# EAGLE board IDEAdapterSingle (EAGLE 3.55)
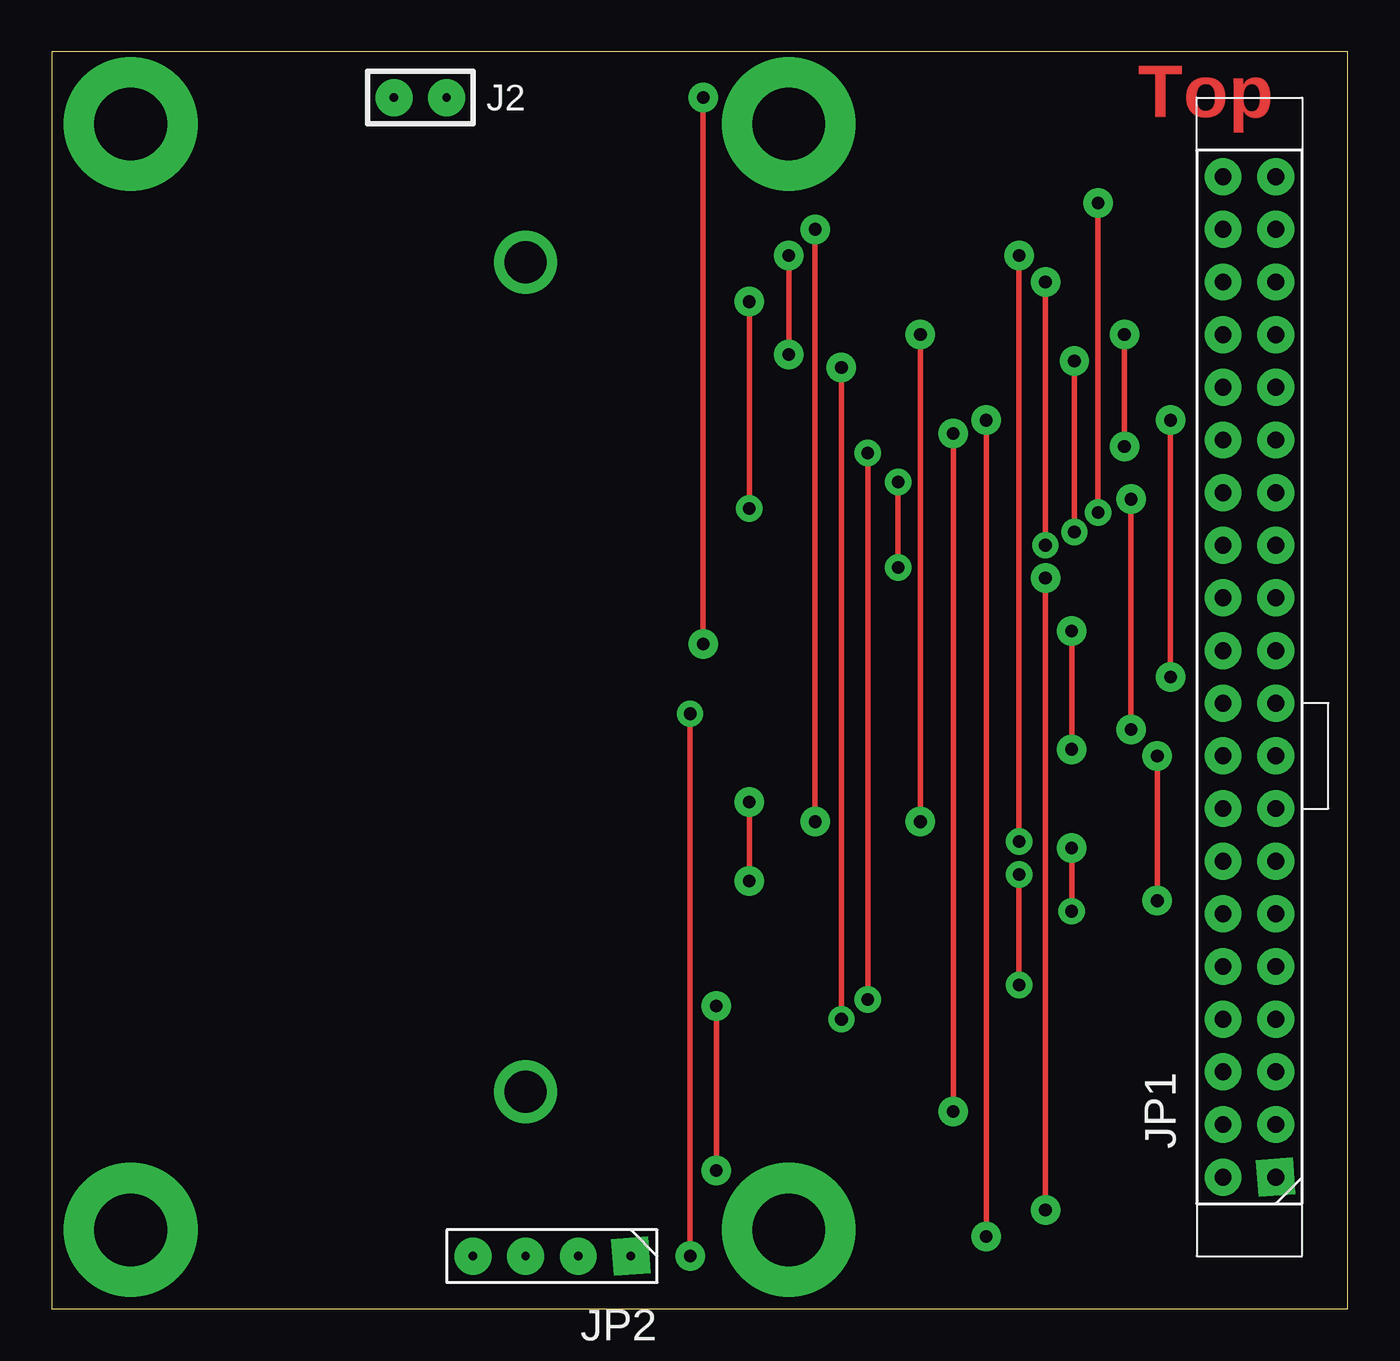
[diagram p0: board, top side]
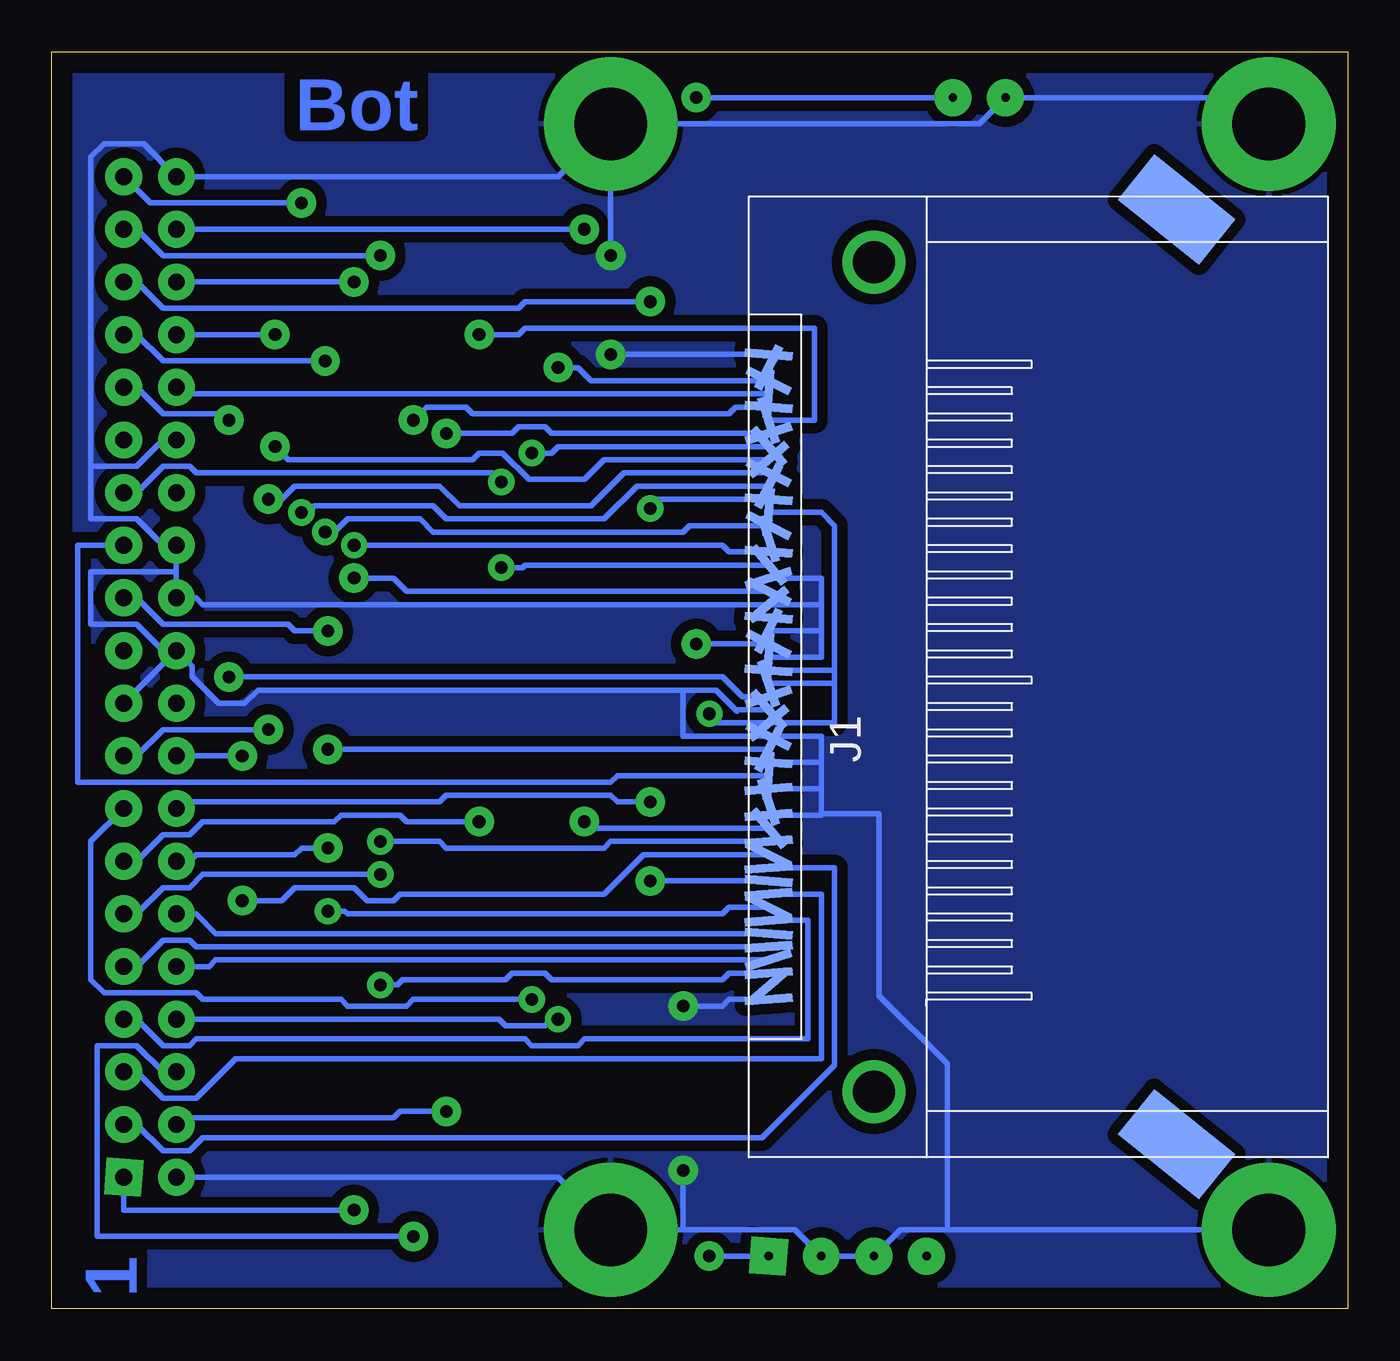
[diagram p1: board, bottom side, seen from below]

Size 62.53 x 60.63 mm. Coordinates in mm from the lower left corner, seen from the top.
Outline: 0,0 62.53,0 62.53,60.63 0,60.63 0,0
Copper layers used: Top, Bottom

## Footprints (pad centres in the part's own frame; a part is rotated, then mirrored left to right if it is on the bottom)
SMT = drill 2.032 pad 3.048 round: @1 -20.003,-5.08; @2 20.003,-5.08 | smd 2.794 x 5.004 rotated 321.2: @3 -22.543,-19.685; @4 22.543,-19.685 | smd 0.406 x 2.311 rotated 4.3:  -15.557,0;  -4.128,0 | smd 0.406 x 2.311 rotated 4.4:  -14.287,0;  8.572,0 | smd 0.406 x 2.311 rotated 4.5:  -13.018,0;  -9.842,0 | smd 0.406 x 2.311 rotated 4.6:  -11.748,0;  2.857,0 | smd 0.406 x 2.311 rotated 4.7:  -10.477,0;  -9.207,0;  15.557,0 | smd 0.406 x 2.311 rotated 4.8:  -7.938,0 | smd 0.406 x 2.311 rotated 4.9:  -6.668,0 | smd 0.406 x 2.311 rotated 5:  -5.397,0 | smd 0.406 x 2.311 rotated 26.8:  -2.857,0 | smd 0.406 x 2.311 rotated 49.3:  -1.587,0 | smd 0.406 x 2.311 rotated 71.8:  -0.318,0 | smd 0.406 x 2.311 rotated 94.3:  0.953,0 | smd 0.406 x 2.311 rotated 116.8:  2.223,0 | smd 0.406 x 2.311 rotated 139.3:  3.493,0 | smd 0.406 x 2.311 rotated 161.8:  4.763,0 | smd 0.406 x 2.311 rotated 184.3:  6.032,0 | smd 0.406 x 2.311 rotated 206.8:  7.303,0 | smd 0.406 x 2.311 rotated 26.9:  9.842,0 | smd 0.406 x 2.311 rotated 49.4:  11.113,0 | smd 0.406 x 2.311 rotated 71.9:  12.383,0 | smd 0.406 x 2.311 rotated 94.4:  13.652,0 | smd 0.406 x 2.311 rotated 116.9:  14.922,0 | smd 0.406 x 2.311 rotated 139.4:  -14.922,0 | smd 0.406 x 2.311 rotated 161.9:  -13.652,0 | smd 0.406 x 2.311 rotated 184.4:  -12.383,0 | smd 0.406 x 2.311 rotated 206.9:  -11.113,0 | smd 0.406 x 2.311 rotated 27:  -8.572,0 | smd 0.406 x 2.311 rotated 49.5:  -7.303,0 | smd 0.406 x 2.311 rotated 72:  -6.032,0 | smd 0.406 x 2.311 rotated 94.5:  -4.763,0 | smd 0.406 x 2.311 rotated 117:  -3.493,0 | smd 0.406 x 2.311 rotated 139.5:  -2.223,0 | smd 0.406 x 2.311 rotated 162:  -0.953,0 | smd 0.406 x 2.311 rotated 184.5:  0.318,0 | smd 0.406 x 2.311 rotated 207:  1.587,0 | smd 0.406 x 2.311 rotated 27.1:  4.128,0 | smd 0.406 x 2.311 rotated 49.6:  5.397,0 | smd 0.406 x 2.311 rotated 72.1:  6.668,0 | smd 0.406 x 2.311 rotated 94.6:  7.938,0 | smd 0.406 x 2.311 rotated 117.1:  9.207,0 | smd 0.406 x 2.311 rotated 139.6:  10.477,0 | smd 0.406 x 2.311 rotated 162.1:  11.748,0 | smd 0.406 x 2.311 rotated 184.6:  13.018,0 | smd 0.406 x 2.311 rotated 207.1:  14.287,0
MPER = drill 0.406 pad 1.778 round:  -1.27,0;  1.27,0
20 = drill 0.813 pad 1.778 square:  -20.32,-1.27 | drill 0.813 pad 1.778 round:  -17.78,-1.27;  -15.24,-1.27;  -12.7,-1.27;  -10.16,-1.27;  -7.62,-1.27;  -5.08,-1.27;  -5.08,1.27;  -7.62,1.27;  -10.16,1.27;  -12.7,1.27;  -15.24,1.27;  -17.78,1.27;  -20.32,1.27;  -2.54,-1.27;  -2.54,1.27;  0,-1.27;  0,1.27;  2.54,-1.27;  2.54,1.27;  5.08,-1.27;  5.08,1.27;  7.62,-1.27;  7.62,1.27;  10.16,-1.27;  10.16,1.27;  12.7,-1.27;  12.7,1.27;  15.24,-1.27;  15.24,1.27;  17.78,-1.27;  17.78,1.27;  20.32,-1.27;  20.32,1.27;  22.86,-1.27;  22.86,1.27;  25.4,-1.27;  25.4,1.27;  27.94,-1.27;  27.94,1.27
4 = drill 0.406 pad 1.778 square:  0,0 | drill 0.406 pad 1.778 round:  5.08,0;  7.62,0;  2.54,0
HRUNG = drill 3.505 pad 6.452 round:  0,0

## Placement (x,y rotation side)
J1  CFLASH1  [SMT]  27.94,30.48 90 bottom
J2  JUMPER  [MPER]  17.78,58.42 0 top
JP1  PINHD-2X20  [20]  57.78,26.67 90 top
JP2  PINHD-1X4  [4]  27.94,2.54 180 top
U$13  BOHRUNG  [HRUNG]  3.81,3.81 0 top
U$14  BOHRUNG  [HRUNG]  3.81,57.15 0 top
U$16  BOHRUNG  [HRUNG]  35.56,57.15 0 top
U$17  BOHRUNG  [HRUNG]  35.56,3.81 0 top

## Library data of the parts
J1 = ic_holg
J2 JP1 JP2 = holg_plt
U$13 U$14 U$16 U$17 = holgnorm

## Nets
+5V: J1. JP2.
/CE1: J1. JP1.
/CE2: J1. JP1.
/DASP: J1. JP1.
/IOCS16: J1. JP1.
/IORD: J1. JP1.
/IOWR: J1. JP1.
/RESET: J1. JP1.
GND: J1. J2. JP1. JP2. U$13. U$14. U$16. U$17.
HA0: J1. JP1.
HA1: J1. JP1.
HA2: J1. JP1.
HD0: J1. JP1.
HD1: J1. JP1.
HD2: J1. JP1.
HD3: J1. JP1.
HD4: J1. JP1.
HD5: J1. JP1.
HD6: J1. JP1.
HD7: J1. JP1.
HD8: J1. JP1.
HD9: J1. JP1.
HD10: J1. JP1.
HD11: J1. JP1.
HD12: J1. JP1.
HD13: J1. JP1.
HD14: J1. JP1.
HD15: J1. JP1.
IORDY: J1. JP1.
IRQ: J1. JP1.
MAS/SLA: J1. J2.
PDIAG: J1. JP1.

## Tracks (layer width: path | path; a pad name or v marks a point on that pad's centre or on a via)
+5V  (via drill 0.61 pad 1.27, 0.61 pad 1.42)
  Top 0.254: v30.8,2.54 v30.8,28.7
  Bottom 0.254: 24.77,30.16 24.77,28.26 27.94,28.26 30.48,28.26 30.48,28.32 30.8,28.64 v30.8,28.7 | 24.77,30.16 27.94,30.16 | 24.77,30.16 24.77,30.8 | 24.77,30.8 27.94,30.8 | 24.77,30.8 24.77,37.78 25.4,38.42 27.94,38.42 | 27.94,2.54 v30.8,2.54
/CE1  (via drill 0.61 pad 1.27, 0.61 pad 1.42)
  Top 0.254: v46.67,22.54 v46.67,50.8
  Bottom 0.254: v46.67,50.8 57.15,50.8 58.42,52.07 59.05,52.07 | 27.94,22.54 35.56,22.54 35.88,22.23 43.5,22.23 43.81,22.54 v46.67,22.54
/CE2  (via drill 0.61 pad 1.42)
  Top 0.254: v36.83,23.5 v36.83,52.07
  Bottom 0.254: v36.83,52.07 56.52,52.07 | v36.83,23.5 36.51,23.18 27.94,23.18
/DASP  (via drill 0.61 pad 1.27, 0.61 pad 1.42)
  Top 0.254: v50.48,38.42 v50.48,53.34
  Bottom 0.254: v50.48,38.42 50.16,38.42 49.85,38.73 44.13,38.73 43.5,38.1 35.88,38.1 34.29,39.69 27.94,39.69 | 59.05,54.61 57.78,53.34 v50.48,53.34
/IOCS16
  Bottom 0.254: 27.94,44.13 55.88,44.13 56.2,44.45 56.52,44.45
/IORD
  Bottom 0.254: 27.94,25.72 35.24,25.72 35.56,25.4 61.28,25.4 61.28,36.83 59.05,36.83
/IOWR  (via drill 0.61 pad 1.42)
  Top 0.254: v49.21,26.99 v49.21,32.7
  Bottom 0.254: v49.21,32.7 50.8,32.7 51.12,33.02 57.15,33.02 58.42,34.29 59.05,34.29 | 27.94,26.99 v49.21,26.99
/RESET  (via drill 0.61 pad 1.42)
  Top 0.254: v47.94,4.76 v47.94,35.24
  Bottom 0.254: v47.94,35.24 46.04,35.24 45.4,34.61 27.94,34.61 | v47.94,4.76 59.05,4.76 59.05,6.35
GND  (via drill 0.61 pad 1.42)
  Top 0.254: v32.07,6.67 v32.07,14.61 | v35.56,50.8 v35.56,46.04
  Bottom 0.254: 56.52,6.35 38.1,6.35 U$17. 32.07,3.81 | 25.4,25.08 27.94,25.08 | 25.4,25.08 25.4,26.35 | 25.4,26.35 27.94,26.35 | 25.4,26.35 25.4,27.62 27.94,27.62 32.07,27.62 32.07,29.84 30.48,29.84 | v32.07,14.61 30.16,14.61 29.84,14.92 27.94,14.92 | U$13. 19.3,3.81 | 19.3,3.81 21.59,3.81 22.86,2.54 JP2. 26.67,3.81 32.07,3.81 | 25.4,32.7 25.4,31.43 27.94,31.43 | 25.4,32.7 27.94,32.7 | 25.4,33.97 25.4,32.7 | 25.4,33.97 27.94,33.97 55.24,33.97 55.56,34.29 56.52,34.29 | 25.4,33.97 25.4,35.24 27.94,35.24 | 56.52,31.75 59.05,29.21 | U$14. 5.08,58.42 16.51,58.42 17.78,57.15 U$16. | v35.56,46.04 J1. | U$16. 38.1,54.61 JP1. 58.1,56.2 60.01,56.2 60.64,55.56 60.64,40.64 | 56.52,31.75 57.15,31.75 58.42,33.02 60.64,33.02 60.64,35.56 56.52,35.56 56.52,34.29 | 56.52,34.29 56.52,36.83 57.15,36.83 58.42,38.1 60.64,38.1 60.64,40.64 | 56.52,41.91 57.15,41.91 58.42,40.64 60.64,40.64 | 30.48,29.84 29.53,28.89 27.94,28.89 29.46,28.89 29.46,28.83 30.48,29.84 | 25.4,23.88 25.4,23.81 27.94,23.81 25.46,23.81 25.4,23.88 | 25.4,23.88 25.4,25.08 | 32.07,3.81 v32.07,6.67 | U$16. v35.56,50.8 | 30.48,29.84 52.58,29.84 53.21,29.21 54.48,29.21 55.75,30.48 55.75,30.99 56.52,31.75 | 25.4,23.88 22.61,23.88 22.61,15.11 19.3,11.81 19.3,3.81
  pour Bottom (isolate 0.508): 0.64,60.33 0.64,0.64 62.23,0.64 62.23,60.33
HA0  (via drill 0.61 pad 1.27, 0.61 pad 1.42)
  Top 0.254: v33.66,38.61 v33.66,48.58
  Bottom 0.254: v33.66,48.58 39.69,48.58 40.01,48.26 57.15,48.26 58.42,49.53 59.05,49.53 | 27.94,39.05 33.34,39.05 33.66,38.73 v33.66,38.61
HA1  (via drill 0.61 pad 1.27, 0.61 pad 1.42)
  Top 0.254: v49.34,37.47 v49.34,45.72
  Bottom 0.254: v49.34,45.72 57.15,45.72 58.42,46.99 59.05,46.99 | 27.94,37.78 31.75,37.78 32.07,37.47 44.13,37.47 44.77,38.1 48.26,38.1 48.9,37.47 v49.34,37.47
HA2  (via drill 0.61 pad 1.27, 0.61 pad 1.42)
  Top 0.254: v47.94,36.83 v47.94,49.53
  Bottom 0.254: v47.94,36.83 30.16,36.83 29.84,36.51 27.94,36.51 | v47.94,49.53 56.52,49.53
HD0  (via drill 0.61 pad 1.42)
  Top 0.254: v52.07,39.05 v52.07,27.94
  Bottom 0.254: v52.07,39.05 51.44,39.05 50.8,39.69 43.81,39.69 42.86,38.73 36.51,38.73 34.92,40.32 27.94,40.32 | v52.07,27.94 57.15,27.94 58.42,26.67 59.05,26.67
HD1  (via drill 0.61 pad 1.27)
  Top 0.254: v39.37,14.92 v39.37,41.27
  Bottom 0.254: v39.37,41.27 38.42,41.27 38.1,41.59 27.94,41.59 | 59.05,24.13 60.64,22.54 60.64,15.88 60.01,15.24 55.56,15.24 55.24,14.92 48.58,14.92 48.26,14.61 45.4,14.61 45.09,14.92 v39.37,14.92
HD2  (via drill 0.61 pad 1.42)
  Top 0.254: v41.91,23.5 v41.91,46.99
  Bottom 0.254: v41.91,46.99 40.01,46.99 39.69,47.31 25.72,47.31 25.72,42.86 27.94,42.86 | v41.91,23.5 45.4,23.5 45.72,23.81 48.58,23.81 48.9,23.5 55.24,23.5 55.88,22.86 57.15,22.86 58.42,21.59 59.05,21.59
HD3  (via drill 0.61 pad 1.27)
  Top 0.254: v46.67,15.62 v46.67,20.95
  Bottom 0.254: v46.67,20.95 55.24,20.95 55.88,20.32 57.15,20.32 58.42,19.05 59.05,19.05 | 27.94,16.19 29.84,16.19 30.16,15.88 38.42,15.88 38.73,16.19 40.32,16.19 40.64,15.88 45.59,15.88 45.85,15.62 v46.67,15.62
HD4
  Bottom 0.254: 27.94,17.46 55.56,17.46 55.88,17.78 57.15,17.78 58.42,16.51 59.05,16.51
HD5
  Bottom 0.254: 27.94,18.73 26.04,18.73 26.04,13.02 36.83,13.02 37.15,12.7 39.37,12.7 39.69,13.02 55.56,13.02 55.88,12.7 57.15,12.7 58.42,13.97 59.05,13.97
HD6
  Bottom 0.254: 27.94,20 25.4,20 25.4,12.06 53.66,12.06 55.56,10.16 57.15,10.16 58.42,11.43 59.05,11.43
HD7
  Bottom 0.254: 27.94,21.27 24.77,21.27 24.77,11.75 28.26,8.26 55.24,8.26 55.88,7.62 57.15,7.62 58.42,8.89 59.05,8.89
HD8  (via drill 0.61 pad 1.42)
  Top 0.254: v43.5,9.53 v43.5,42.23
  Bottom 0.254: v43.5,42.23 40.32,42.23 40.01,42.55 38.73,42.55 38.42,42.23 27.94,42.23 | v43.5,9.53 45.72,9.53 46.04,9.21 56.2,9.21 56.52,8.89
HD9  (via drill 0.61 pad 1.42)
  Top 0.254: v45.09,3.49 v45.09,42.86
  Bottom 0.254: v45.09,3.49 60.33,3.49 60.33,12.7 58.42,12.7 57.15,11.43 56.52,11.43 | v45.09,42.86 44.45,43.5 42.55,43.5 42.23,43.18 29.84,43.18 29.53,43.5 27.94,43.5
HD10  (via drill 0.61 pad 1.27, 0.61 pad 1.42)
  Top 0.254: v38.1,13.97 v38.1,45.4
  Bottom 0.254: v38.1,13.97 38.42,13.97 38.73,13.65 40.64,13.65 40.96,13.97 56.52,13.97 | v38.1,45.4 37.15,45.4 36.51,44.77 27.94,44.77
HD11
  Bottom 0.254: 27.94,16.83 54.61,16.83 54.93,16.51 56.52,16.51
HD12
  Bottom 0.254: 27.94,18.1 54.61,18.1 55.56,19.05 56.52,19.05
HD13  (via drill 0.61 pad 1.27, 0.61 pad 1.42)
  Top 0.254: v49.21,19.18 v49.21,22.23
  Bottom 0.254: 27.94,19.37 29.84,19.37 30.16,19.05 48.26,19.05 48.39,19.18 v49.21,19.18 | v49.21,22.23 50.48,22.23 50.8,21.91 55.56,21.91 55.88,21.59 56.52,21.59
HD14  (via drill 0.61 pad 1.42)
  Top 0.254: v33.66,20.64 v33.66,24.45
  Bottom 0.254: v33.66,24.45 35.24,24.45 35.56,24.77 43.5,24.77 43.81,24.45 55.88,24.45 56.2,24.13 56.52,24.13 | 27.94,20.64 v33.66,20.64
HD15  (via drill 0.61 pad 1.42)
  Top 0.254: v53.34,19.68 v53.34,26.67
  Bottom 0.254: v53.34,19.68 51.44,19.68 50.8,20.32 47.94,20.32 47.31,19.68 46.04,19.68 45.72,20 35.88,20 33.97,21.91 27.94,21.91 | v53.34,26.67 56.52,26.67
IORDY  (via drill 0.61 pad 1.27)
  Top 0.254: v40.83,35.75 v40.83,39.88
  Bottom 0.254: 59.05,39.37 58.42,39.37 57.15,40.64 55.88,40.64 55.56,40.32 41.27,40.32 v40.83,39.88 | v40.83,35.75 39.81,35.75 39.69,35.88 27.94,35.88
IRQ  (via drill 0.61 pad 1.42)
  Top 0.254: v53.98,30.48 v53.98,42.86
  Bottom 0.254: v53.98,30.48 30.16,30.48 29.21,29.53 27.94,29.53 | v53.98,42.86 54.29,43.18 57.15,43.18 58.42,44.45 59.05,44.45
MAS/SLA  (via drill 0.61 pad 1.42)
  Top 0.254: v31.43,32.07 v31.43,58.42
  Bottom 0.254: 27.94,32.07 v31.43,32.07 | v31.43,58.42 J2.
PDIAG  (via drill 0.61 pad 1.42)
  Top 0.254: v51.75,41.59 v51.75,46.99
  Bottom 0.254: v51.75,41.59 51.12,40.96 42.23,40.96 41.91,41.27 40.77,41.27 39.5,40.01 36.83,40.01 35.88,40.96 27.94,40.96 | v51.75,46.99 56.52,46.99

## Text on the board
Top: Top
Bottom: Bot | 1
